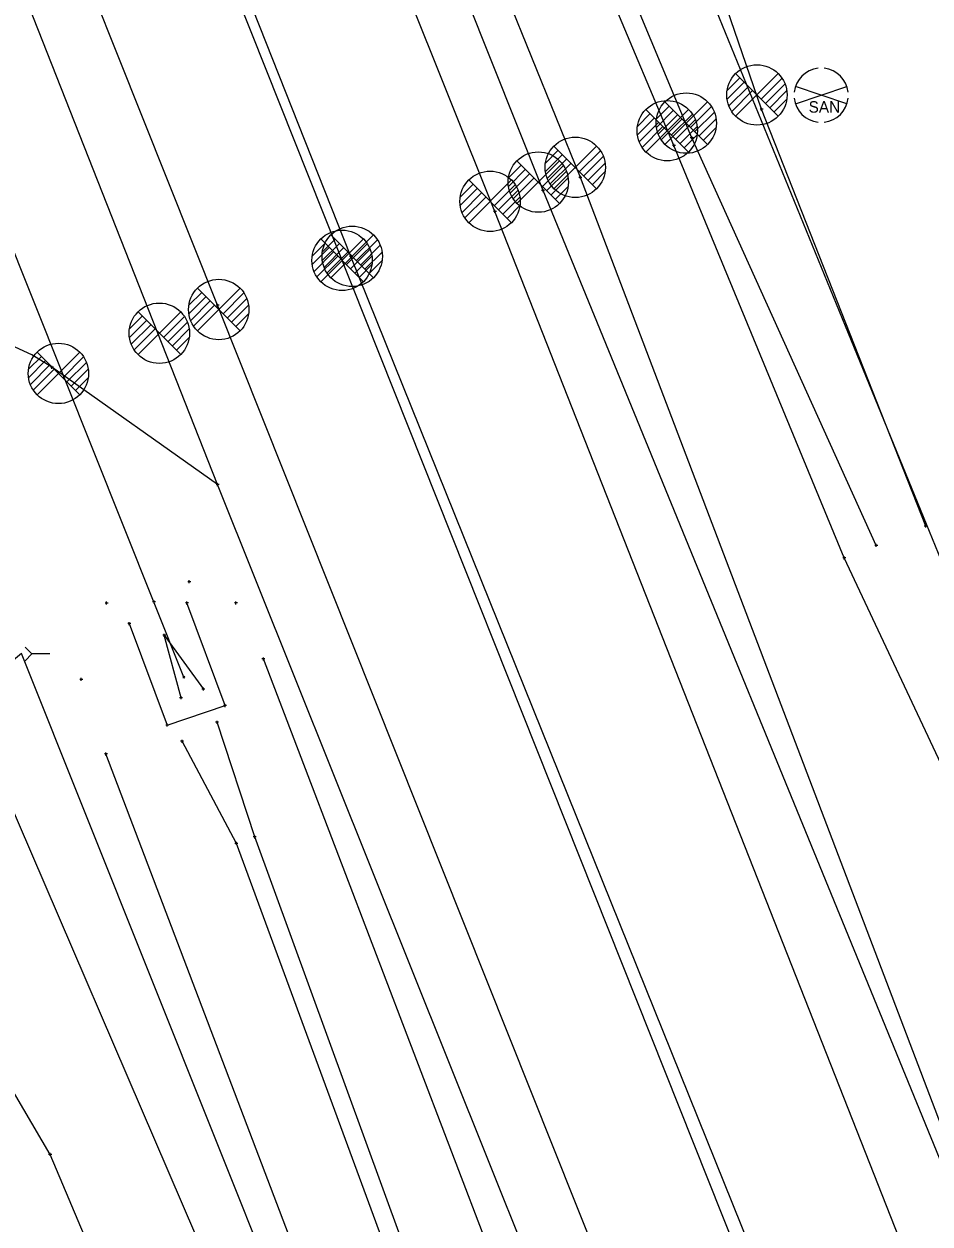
# Model space of a CAD drawing. Extents: x 1954856 to 2011933, y 399149 to 426294.
# Drawn here: x 2004595.4 to 2004670.5, y 408723.4 to 408822.7 of the extents above; entities that cross this region are included whole.
import ezdxf

# ---------------------------------------------------------------- set-up
doc = ezdxf.new("R2010")
doc.units = 0
for name, color, linetype in [('BankMent_ep', 7, 'Continuous'), ('BaselineSurvey', 7, 'Continuous'), ('Driveway_ep', 7, 'Continuous'), ('ElecAer_ep', 7, 'Continuous'), ('EndTreatMES_ep', 7, 'Continuous'), ('FlowLineInvert_ep', 7, 'Continuous'), ('PavtAsphalt_ep', 7, 'Continuous'), ('PavtAsphaltCrown_ep', 7, 'Continuous'), ('PipeCulvert_ep', 7, 'Continuous'), ('PointLocator_ep', 7, 'Continuous'), ('PoleShared_ep', 7, 'Continuous'), ('ShldrPaved_ep', 7, 'Continuous'), ('TreeLineScatter_ep', 7, 'Continuous'), ('ValveCvrSewer_ep', 7, 'Continuous'), ('XSPt_ep', 7, 'Continuous')]:
    doc.layers.add(name, color=color, linetype=linetype)

msp = doc.modelspace()

# ---------------------------------------------------------------- linework, layer by layer
at = {"layer": 'BankMent_ep'}
for p, q in [((2004656.524, 408815.656), (2004624.084, 408910.017)), ((2004649.266, 408812.663), (2004610.288, 408905.027)), ((2004641.516, 408810.016), (2004604.017, 408902.465)), ((2004670.127, 408781.139), (2004656.524, 408815.656)), ((2004663.377, 408778.514), (2004649.266, 408812.663)), ((2004671.654, 408730.864), (2004641.516, 408810.016)), ((2004681.002, 408740.93), (2004663.377, 408778.514)), ((2004640.703, 408703.541), (2004615.253, 408770.148)), ((2004626.551, 408698.266), (2004602.201, 408762.278))]:
    msp.add_line(p, q, dxfattribs=at)
for points in [[(2004666.03, 408779.537), (2004650.747, 408813.305), (2004612.23, 408905.481), (2004573.588, 408998.689), (2004539.669, 409093.742), (2004502.481, 409185.919), (2004466.319, 409279.22), (2004430.042, 409371.413), (2004392.893, 409464.298), (2004356.121, 409557.463), (2004319.2, 409650.335)], [(2004650.707, 408663.871), (2004643.599, 408678.783), (2004634.281, 408701.227), (2004614.532, 408755.402), (2004611.416, 408764.9)], [(2004648.371, 408662.67), (2004641.986, 408677.623), (2004633.012, 408700.588), (2004613.007, 408754.869), (2004608.511, 408763.331)]]:
    msp.add_lwpolyline(points, dxfattribs=at)
at = {"layer": 'BaselineSurvey'}
msp.add_line((2004967.712, 407935.044), (2004043.601, 410254.038), dxfattribs=at)
msp.add_line((2004967.712, 407935.044), (2004043.601, 410254.038), dxfattribs=at)
at = {"layer": 'Driveway_ep'}
for p, q in [((2004611.459, 408784.574), (2004597.729, 408794.296)), ((2004597.582, 408729.107), (2004581.507, 408756.44)), ((2004612.654, 408693.538), (2004597.582, 408729.107))]:
    msp.add_line(p, q, dxfattribs=at)
for points in [[(2004597.729, 408794.296), (2004596.067, 408795.325), (2004594.326, 408796.136), (2004592.523, 408796.75), (2004590.674, 408797.192), (2004588.794, 408797.482), (2004586.9, 408797.643), (2004583.934, 408797.685), (2004580.975, 408797.516), (2004578.03, 408797.188), (2004575.1, 408796.749), (2004568.51, 408795.506), (2004562.025, 408793.932), (2004555.644, 408792.009), (2004549.364, 408789.717), (2004543.184, 408787.036), (2004537.102, 408783.945), (2004531.117, 408780.426), (2004525.227, 408776.458)], [(2004641.286, 408633.179), (2004634.007, 408661.99), (2004621.03, 408695.971), (2004581.266, 408788.354), (2004575.1, 408796.749)]]:
    msp.add_lwpolyline(points, dxfattribs=at)
at = {"layer": 'ElecAer_ep'}
msp.add_lwpolyline([(2004669.714, 408584.232), (2004595.203, 408770.583), (2004546.471, 408730.084)], dxfattribs=at)
at = {"layer": 'EndTreatMES_ep'}
for p, q in [((2004612.078, 408766.278), (2004608.918, 408774.778)), ((2004604.141, 408773.072), (2004607.287, 408764.666)), ((2004607.287, 408764.666), (2004612.078, 408766.278))]:
    msp.add_line(p, q, dxfattribs=at)
msp.add_lwpolyline([(2004608.424, 408766.933), (2004607.031, 408772.104), (2004610.285, 408767.652)], dxfattribs=at)
at = {"layer": 'FlowLineInvert_ep'}
for p, q in [((2004608.747, 408768.541), (2004608.571, 408768.717)), ((2004608.747, 408768.717), (2004608.571, 408768.541)), ((2004608.659, 408768.629), (2004608.659, 408768.629))]:
    msp.add_line(p, q, dxfattribs=at)
at = {"layer": 'PavtAsphalt_ep'}
for points in [[(2004930.287, 408065.103), (2004893.538, 408157.667), (2004856.383, 408250.558), (2004819.209, 408343.482), (2004782.128, 408435.872), (2004745.095, 408528.975), (2004708.037, 408621.605), (2004670.836, 408714.83), (2004634.433, 408807.202), (2004597.182, 408900.115), (2004560.233, 408993.393), (2004523.085, 409086.647), (2004486.253, 409179.549), (2004449.348, 409272.321), (2004412.405, 409364.963), (2004375.265, 409458.204), (2004338.192, 409550.484), (2004300.954, 409644.078)], [(2004908.031, 408056.318), (2004870.866, 408148.946), (2004833.864, 408242.039), (2004796.664, 408334.537), (2004759.706, 408427.582), (2004722.747, 408520.319), (2004685.696, 408613.316), (2004648.57, 408706.423), (2004611.452, 408799.434), (2004574.348, 408892.333), (2004537.272, 408984.581), (2004500.453, 409078.034), (2004463.689, 409170.998), (2004426.246, 409264.134), (2004389.643, 409356.859), (2004352.627, 409449.557), (2004314.973, 409542.013), (2004278.206, 409635.443)]]:
    msp.add_lwpolyline(points, dxfattribs=at)
at = {"layer": 'PavtAsphaltCrown_ep'}
msp.add_lwpolyline([(2004919.301, 408060.523), (2004882.31, 408153.481), (2004845.118, 408246.237), (2004807.96, 408339.119), (2004770.735, 408431.914), (2004733.823, 408525.035), (2004696.728, 408617.52), (2004659.9, 408710.758), (2004622.497, 408803.468), (2004585.743, 408896.215), (2004548.969, 408989.346), (2004511.742, 409082.341), (2004474.908, 409175.322), (2004437.746, 409268.102), (2004401.035, 409361.084), (2004363.749, 409453.876), (2004326.648, 409546.703), (2004289.563, 409639.687)], dxfattribs=at)
at = {"layer": 'PipeCulvert_ep'}
msp.add_lwpolyline([(2004608.659, 408768.629), (2004571.207, 408862.365)], dxfattribs=at)
at = {"layer": 'PointLocator_ep'}
for p, q in [((2004656.649, 408815.656), (2004656.399, 408815.656)), ((2004656.524, 408815.531), (2004656.524, 408815.781)), ((2004656.524, 408815.656), (2004656.524, 408815.656)), ((2004650.872, 408813.305), (2004650.622, 408813.305)), ((2004650.747, 408813.18), (2004650.747, 408813.43)), ((2004650.747, 408813.305), (2004650.747, 408813.305)), ((2004649.391, 408812.663), (2004649.141, 408812.663)), ((2004649.266, 408812.538), (2004649.266, 408812.788)), ((2004649.266, 408812.663), (2004649.266, 408812.663)), ((2004641.641, 408810.016), (2004641.391, 408810.016)), ((2004641.516, 408809.891), (2004641.516, 408810.141)), ((2004641.516, 408810.016), (2004641.516, 408810.016)), ((2004638.423, 408808.794), (2004638.423, 408809.044)), ((2004638.548, 408808.919), (2004638.298, 408808.919)), ((2004638.423, 408808.919), (2004638.423, 408808.919)), ((2004634.558, 408807.202), (2004634.308, 408807.202)), ((2004634.433, 408807.077), (2004634.433, 408807.327)), ((2004634.433, 408807.202), (2004634.433, 408807.202)), ((2004622.622, 408803.468), (2004622.372, 408803.468)), ((2004622.497, 408803.343), (2004622.497, 408803.593)), ((2004622.497, 408803.468), (2004622.497, 408803.468)), ((2004611.577, 408799.434), (2004611.327, 408799.434)), ((2004611.452, 408799.309), (2004611.452, 408799.559)), ((2004611.452, 408799.434), (2004611.452, 408799.434)), ((2004597.854, 408794.296), (2004597.604, 408794.296)), ((2004597.729, 408794.171), (2004597.729, 408794.421)), ((2004597.729, 408794.296), (2004597.729, 408794.296)), ((2004611.584, 408784.574), (2004611.334, 408784.574)), ((2004611.459, 408784.449), (2004611.459, 408784.699)), ((2004611.459, 408784.574), (2004611.459, 408784.574)), ((2004670.252, 408781.139), (2004670.002, 408781.139)), ((2004670.127, 408781.014), (2004670.127, 408781.264)), ((2004670.127, 408781.139), (2004670.127, 408781.139)), ((2004666.155, 408779.537), (2004665.905, 408779.537)), ((2004666.03, 408779.412), (2004666.03, 408779.662)), ((2004666.03, 408779.537), (2004666.03, 408779.537)), ((2004663.502, 408778.514), (2004663.252, 408778.514)), ((2004663.377, 408778.389), (2004663.377, 408778.639)), ((2004663.377, 408778.514), (2004663.377, 408778.514)), ((2004609.225, 408776.533), (2004608.975, 408776.533)), ((2004609.1, 408776.408), (2004609.1, 408776.658)), ((2004609.1, 408776.533), (2004609.1, 408776.533)), ((2004602.378, 408774.766), (2004602.128, 408774.766)), ((2004602.253, 408774.641), (2004602.253, 408774.891)), ((2004602.253, 408774.766), (2004602.253, 408774.766)), ((2004606.323, 408774.864), (2004606.073, 408774.864)), ((2004606.198, 408774.739), (2004606.198, 408774.989)), ((2004606.198, 408774.864), (2004606.198, 408774.864)), ((2004609.043, 408774.778), (2004608.793, 408774.778)), ((2004608.918, 408774.653), (2004608.918, 408774.903)), ((2004608.918, 408774.778), (2004608.918, 408774.778)), ((2004613.092, 408774.776), (2004612.842, 408774.776)), ((2004612.967, 408774.651), (2004612.967, 408774.901)), ((2004612.967, 408774.776), (2004612.967, 408774.776)), ((2004604.141, 408772.947), (2004604.141, 408773.197)), ((2004604.266, 408773.072), (2004604.016, 408773.072)), ((2004604.141, 408773.072), (2004604.141, 408773.072)), ((2004607.031, 408771.979), (2004607.031, 408772.229)), ((2004607.156, 408772.104), (2004606.906, 408772.104)), ((2004607.031, 408772.104), (2004607.031, 408772.104)), ((2004615.253, 408770.023), (2004615.253, 408770.273)), ((2004615.378, 408770.148), (2004615.128, 408770.148)), ((2004615.253, 408770.148), (2004615.253, 408770.148)), ((2004600.288, 408768.45), (2004600.038, 408768.45)), ((2004600.163, 408768.325), (2004600.163, 408768.575)), ((2004600.163, 408768.45), (2004600.163, 408768.45)), ((2004610.41, 408767.652), (2004610.16, 408767.652)), ((2004610.285, 408767.527), (2004610.285, 408767.777)), ((2004610.285, 408767.652), (2004610.285, 408767.652)), ((2004608.549, 408766.933), (2004608.299, 408766.933)), ((2004608.424, 408766.808), (2004608.424, 408767.058)), ((2004608.424, 408766.933), (2004608.424, 408766.933)), ((2004612.203, 408766.278), (2004611.953, 408766.278)), ((2004612.078, 408766.153), (2004612.078, 408766.403)), ((2004612.078, 408766.278), (2004612.078, 408766.278)), ((2004607.412, 408764.666), (2004607.162, 408764.666)), ((2004607.287, 408764.541), (2004607.287, 408764.791)), ((2004607.287, 408764.666), (2004607.287, 408764.666)), ((2004611.541, 408764.9), (2004611.291, 408764.9)), ((2004611.416, 408764.775), (2004611.416, 408765.025)), ((2004611.416, 408764.9), (2004611.416, 408764.9)), ((2004608.636, 408763.331), (2004608.386, 408763.331)), ((2004608.511, 408763.206), (2004608.511, 408763.456)), ((2004608.511, 408763.331), (2004608.511, 408763.331)), ((2004602.326, 408762.278), (2004602.076, 408762.278)), ((2004602.201, 408762.153), (2004602.201, 408762.403)), ((2004602.201, 408762.278), (2004602.201, 408762.278)), ((2004614.657, 408755.402), (2004614.407, 408755.402)), ((2004614.532, 408755.277), (2004614.532, 408755.527)), ((2004614.532, 408755.402), (2004614.532, 408755.402)), ((2004613.132, 408754.869), (2004612.882, 408754.869)), ((2004613.007, 408754.744), (2004613.007, 408754.994)), ((2004613.007, 408754.869), (2004613.007, 408754.869)), ((2004597.707, 408729.107), (2004597.457, 408729.107)), ((2004597.582, 408728.982), (2004597.582, 408729.232)), ((2004597.582, 408729.107), (2004597.582, 408729.107))]:
    msp.add_line(p, q, dxfattribs=at)
at = {"layer": 'PoleShared_ep'}
msp.add_line((2004597.565, 408770.558), (2004596.065, 408770.558), dxfattribs=at)
msp.add_lwpolyline([(2004595.499, 408771.124), (2004596.065, 408770.558), (2004595.498, 408769.991)], dxfattribs=at)
at = {"layer": 'ShldrPaved_ep'}
for p, q in [((2004638.423, 408808.919), (2004601.481, 408901.772)), ((2004672.847, 408724.918), (2004638.423, 408808.919))]:
    msp.add_line(p, q, dxfattribs=at)
msp.add_lwpolyline([(2004903.293, 408054.422), (2004866.253, 408147.184), (2004829.784, 408238.432), (2004819.429, 408264.526), (2004792.125, 408332.806), (2004764.061, 408411.253), (2004736.065, 408472.394), (2004723.511, 408503.89), (2004692.556, 408581.578), (2004685.951, 408598.809), (2004662.716, 408655.961), (2004643.532, 408704.544), (2004611.459, 408784.574), (2004586.655, 408847.405), (2004569.698, 408890.518), (2004561.672, 408910.22), (2004521.282, 409011.508), (2004496.044, 409076.356), (2004458.966, 409168.823), (2004421.589, 409262.301), (2004384.823, 409355.228), (2004347.845, 409447.988), (2004310.719, 409540.774), (2004273.836, 409633.545)], dxfattribs=at)
at = {"layer": 'TreeLineScatter_ep'}
msp.add_lwpolyline([(2004790.093, 408736.268), (2004698.762, 408711.47), (2004581.18, 408998.73)], dxfattribs=at)
at = {"layer": 'ValveCvrSewer_ep'}
for p, q in [((2004659.329, 408816.11), (2004663.599, 408817.534)), ((2004663.599, 408816.11), (2004659.329, 408817.534)), ((2004661.464, 408816.822), (2004661.464, 408816.822))]:
    msp.add_line(p, q, dxfattribs=at)
for start, end in [(96.37937, 173.62063), (6.37937, 83.62063), (186.37937, 263.62063), (276.37937, 353.62063)]:
    msp.add_arc((2004661.464, 408816.822), 2.25, start, end, dxfattribs=at)
at = {"layer": 'XSPt_ep'}
for p, q in [((2004653.666, 408817.2), (2004654.727, 408818.26)), ((2004653.666, 408816.492), (2004655.08, 408817.907)), ((2004654.373, 408815.078), (2004657.909, 408818.614)), ((2004657.909, 408815.078), (2004654.373, 408818.614)), ((2004656.495, 408816.492), (2004658.227, 408818.224)), ((2004653.814, 408815.933), (2004655.434, 408817.553)), ((2004654.055, 408815.468), (2004655.787, 408817.2)), ((2004656.848, 408816.139), (2004658.468, 408817.759)), ((2004657.202, 408815.785), (2004658.616, 408817.2)), ((2004647.814, 408814.867), (2004648.875, 408815.927)), ((2004648.521, 408812.745), (2004652.057, 408816.281)), ((2004652.057, 408812.745), (2004648.521, 408816.281)), ((2004656.141, 408816.846), (2004656.141, 408816.846)), ((2004657.555, 408815.432), (2004658.616, 408816.492)), ((2004646.235, 408814.238), (2004647.296, 408815.298)), ((2004646.235, 408813.53), (2004647.649, 408814.945)), ((2004646.942, 408812.116), (2004650.478, 408815.652)), ((2004650.478, 408812.116), (2004646.942, 408815.652)), ((2004647.814, 408814.159), (2004649.228, 408815.574)), ((2004647.962, 408813.6), (2004649.582, 408815.22)), ((2004649.064, 408813.53), (2004650.796, 408815.262)), ((2004650.643, 408814.159), (2004652.375, 408815.891)), ((2004650.996, 408813.806), (2004652.616, 408815.426)), ((2004646.383, 408812.971), (2004648.003, 408814.591)), ((2004646.624, 408812.506), (2004648.356, 408814.238)), ((2004648.203, 408813.135), (2004649.935, 408814.867)), ((2004649.417, 408813.177), (2004651.037, 408814.797)), ((2004649.771, 408812.823), (2004651.185, 408814.238)), ((2004650.289, 408814.513), (2004650.289, 408814.513)), ((2004651.35, 408813.452), (2004652.764, 408814.867)), ((2004651.703, 408813.099), (2004652.764, 408814.159)), ((2004648.71, 408813.884), (2004648.71, 408813.884)), ((2004650.124, 408812.47), (2004651.185, 408813.53)), ((2004638.617, 408811.203), (2004639.678, 408812.263)), ((2004639.324, 408809.081), (2004642.86, 408812.617)), ((2004642.86, 408809.081), (2004639.324, 408812.617)), ((2004641.446, 408810.495), (2004643.178, 408812.227)), ((2004635.552, 408809.981), (2004636.613, 408811.041)), ((2004636.259, 408807.859), (2004639.795, 408811.395)), ((2004639.795, 408807.859), (2004636.259, 408811.395)), ((2004638.381, 408809.273), (2004640.113, 408811.005)), ((2004638.617, 408810.495), (2004640.031, 408811.91)), ((2004638.765, 408809.936), (2004640.385, 408811.556)), ((2004639.006, 408809.471), (2004640.738, 408811.203)), ((2004641.799, 408810.142), (2004643.419, 408811.762)), ((2004642.153, 408809.788), (2004643.567, 408811.203)), ((2004635.552, 408809.273), (2004636.966, 408810.688)), ((2004635.7, 408808.714), (2004637.32, 408810.334)), ((2004635.941, 408808.249), (2004637.673, 408809.981)), ((2004638.734, 408808.92), (2004640.354, 408810.54)), ((2004639.088, 408808.566), (2004640.502, 408809.981)), ((2004641.092, 408810.849), (2004641.092, 408810.849)), ((2004642.506, 408809.435), (2004643.567, 408810.495)), ((2004631.557, 408808.389), (2004632.618, 408809.449)), ((2004631.557, 408807.681), (2004632.971, 408809.096)), ((2004632.264, 408806.267), (2004635.8, 408809.803)), ((2004635.8, 408806.267), (2004632.264, 408809.803)), ((2004634.386, 408807.681), (2004636.118, 408809.413)), ((2004638.027, 408809.627), (2004638.027, 408809.627)), ((2004639.441, 408808.213), (2004640.502, 408809.273)), ((2004631.705, 408807.122), (2004633.325, 408808.742)), ((2004631.946, 408806.657), (2004633.678, 408808.389)), ((2004634.032, 408808.035), (2004634.032, 408808.035)), ((2004634.739, 408807.328), (2004636.359, 408808.948)), ((2004635.093, 408806.974), (2004636.507, 408808.389)), ((2004635.446, 408806.621), (2004636.507, 408807.681)), ((2004620.838, 408801.714), (2004624.374, 408805.25)), ((2004624.374, 408801.714), (2004620.838, 408805.25)), ((2004619.295, 408803.503), (2004620.356, 408804.563)), ((2004619.295, 408802.795), (2004620.709, 408804.21)), ((2004620.002, 408801.381), (2004623.538, 408804.917)), ((2004623.538, 408801.381), (2004620.002, 408804.917)), ((2004620.131, 408803.836), (2004621.192, 408804.896)), ((2004620.131, 408803.128), (2004621.545, 408804.543)), ((2004620.279, 408802.569), (2004621.899, 408804.189)), ((2004622.124, 408802.795), (2004623.856, 408804.527)), ((2004622.477, 408802.442), (2004624.097, 408804.062)), ((2004622.96, 408803.128), (2004624.692, 408804.86)), ((2004623.313, 408802.775), (2004624.933, 408804.395)), ((2004619.443, 408802.236), (2004621.063, 408803.856)), ((2004619.684, 408801.771), (2004621.416, 408803.503)), ((2004620.52, 408802.104), (2004622.252, 408803.836)), ((2004621.77, 408803.149), (2004621.77, 408803.149)), ((2004622.606, 408803.482), (2004622.606, 408803.482)), ((2004622.831, 408802.088), (2004624.245, 408803.503)), ((2004623.667, 408802.421), (2004625.081, 408803.836)), ((2004624.02, 408802.068), (2004625.081, 408803.128)), ((2004623.184, 408801.735), (2004624.245, 408802.795)), ((2004609.076, 408799.431), (2004610.137, 408800.491)), ((2004609.076, 408798.723), (2004610.49, 408800.138)), ((2004609.783, 408797.309), (2004613.319, 408800.845)), ((2004613.319, 408797.309), (2004609.783, 408800.845)), ((2004611.905, 408798.723), (2004613.637, 408800.455)), ((2004609.224, 408798.164), (2004610.844, 408799.784)), ((2004609.465, 408797.699), (2004611.197, 408799.431)), ((2004611.551, 408799.077), (2004611.551, 408799.077)), ((2004612.258, 408798.37), (2004613.878, 408799.99)), ((2004612.612, 408798.016), (2004614.026, 408799.431)), ((2004604.153, 408797.469), (2004605.214, 408798.529)), ((2004604.153, 408796.761), (2004605.567, 408798.176)), ((2004604.86, 408795.347), (2004608.396, 408798.883)), ((2004608.396, 408795.347), (2004604.86, 408798.883)), ((2004606.982, 408796.761), (2004608.714, 408798.493)), ((2004607.335, 408796.408), (2004608.955, 408798.028)), ((2004612.965, 408797.663), (2004614.026, 408798.723)), ((2004604.301, 408796.202), (2004605.921, 408797.822)), ((2004604.542, 408795.737), (2004606.274, 408797.469)), ((2004606.628, 408797.115), (2004606.628, 408797.115)), ((2004607.689, 408796.054), (2004609.103, 408797.469)), ((2004608.042, 408795.701), (2004609.103, 408796.761)), ((2004595.792, 408794.137), (2004596.853, 408795.197)), ((2004596.499, 408792.015), (2004600.035, 408795.551)), ((2004600.035, 408792.015), (2004596.499, 408795.551)), ((2004598.621, 408793.429), (2004600.353, 408795.161)), ((2004595.792, 408793.429), (2004597.206, 408794.844)), ((2004595.94, 408792.87), (2004597.56, 408794.49)), ((2004596.181, 408792.405), (2004597.913, 408794.137)), ((2004598.974, 408793.076), (2004600.594, 408794.696)), ((2004599.328, 408792.722), (2004600.742, 408794.137)), ((2004598.267, 408793.783), (2004598.267, 408793.783)), ((2004599.681, 408792.369), (2004600.742, 408793.429))]:
    msp.add_line(p, q, dxfattribs=at)
for centre in [(2004656.141, 408816.846), (2004650.289, 408814.513), (2004648.71, 408813.884), (2004641.092, 408810.849), (2004638.027, 408809.627), (2004634.032, 408808.035), (2004622.606, 408803.482), (2004621.77, 408803.149), (2004611.551, 408799.077), (2004606.628, 408797.115), (2004598.267, 408793.783)]:
    msp.add_circle(centre, 2.5, dxfattribs=at)

# ---------------------------------------------------------------- texts
at = {"layer": 'ValveCvrSewer_ep'}
msp.add_text('SAN', height=0.95, dxfattribs=at).set_placement((2004660.425, 408815.38))

doc.saveas('drawing.dxf')
